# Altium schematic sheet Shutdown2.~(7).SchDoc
size A4
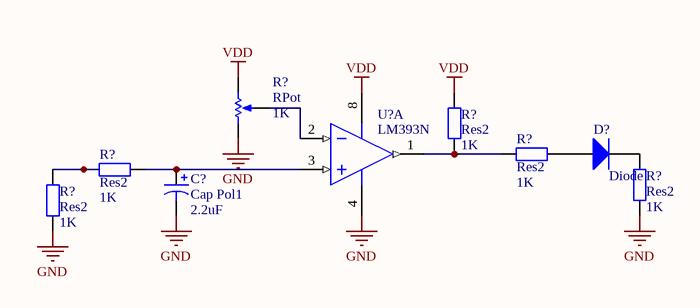
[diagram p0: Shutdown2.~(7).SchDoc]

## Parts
(Parts that share a designator on the sheet are numbered #1, #2 ... from top to bottom, then left to right.)
C?  Cap Pol1  value 2.2uF  [RB7.6-15]
D?  Diode  [SMC]
R?#1  RPot  value 1K  [VR5]
R?#2  Res2  value 1K  [AXIAL-0.4]
R?#3  Res2  value 1K  [AXIAL-0.4]
R?#4  Res2  value 1K  [AXIAL-0.4]
R?#5  Res2  value 1K  [AXIAL-0.4]
R?#6  Res2  value 1K  [AXIAL-0.4]
U?  LM393N  [626-05]  (part A of 2)

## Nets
GND: C?.2 R?#1.1(TOP) R?#5.1 R?#6.1 U?.4(GND)
VDD: R?#1.2(BOT) R?#2.2 U?.8(V+)
NetC?_1: C?.1 R?#4.2 U?.3(IN+)
NetD?_1: D?.1(A) R?#3.2
NetD?_2: D?.2(K) R?#5.2
NetR?#1_3: R?#1.3(TAP) U?.2(IN-)
NetR?#2_1: R?#2.1 R?#3.1 U?.1(OUT)
NetR?#4_1: R?#4.1 R?#6.2

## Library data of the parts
C? = Cap Pol1: Polarized Capacitor (Radial)
D? = Diode: Default Diode
R?#1 = RPot: Potentiometer; Sim Note: Enter the Resistance value and the set point into parameter fields.; Set Position: 0.5
R?#2-R?#6 = Res2: Resistor
U? = LM393N: Dual Comparator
